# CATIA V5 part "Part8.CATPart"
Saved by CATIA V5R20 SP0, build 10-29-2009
Part number: 9CS081215
Revision: ANY
Definition: UNKNOWN
Nomenclature: 9CS081215
Source: Unknown
Bounding box of the stored display mesh (mm): x -5.85 to 5.85, y -7.5 to 7.5, z -6 to 6
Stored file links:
  C:\Users\Utente\Desktop\IO LAVORO\3D X SITO CF\CUMSA\3D files PW\pw081030\pw081030_injection\Part8.CATPart
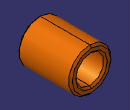
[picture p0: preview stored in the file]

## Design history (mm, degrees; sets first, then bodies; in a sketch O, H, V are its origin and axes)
Body1 "Revolución1" (main body)
  Solid1: solid without history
